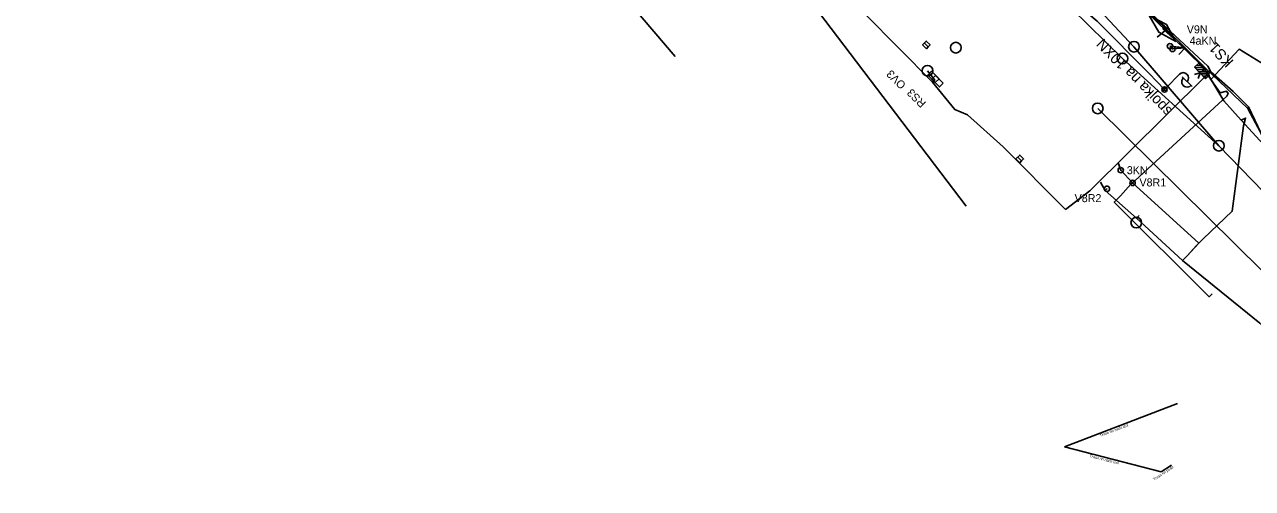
# Model space of a CAD drawing. Extents: x -748507 to -687366, y -1057342 to -1024924.
# Drawn here: x -745165 to -744934.9, y -1030359.4 to -1030272.6 of the extents above; entities that cross this region are included whole.
import ezdxf

# ---------------------------------------------------------------- set-up
doc = ezdxf.new("R2010")
doc.units = 0
for name, color, linetype in [('6kV - SŽDC', 7, 'Continuous'), ('DK + TKK - SŽDC', 7, 'Continuous'), ('DK - Pha Holešovice - Kralupy - ČD TELEMATIKA', 7, 'Continuous'), ('kanalizace ČD', 7, 'Continuous'), ('Sděl MK - SŽDC', 7, 'Continuous'), ('TK+DOK_Pha Holešovice - Kralupy', 7, 'Continuous'), ('Vedení NN - SŽDC', 7, 'Continuous'), ('ČEZ Distribuce - NN', 7, 'Continuous'), ('ČEZ Distribuce - VN', 7, 'Continuous')]:
    doc.layers.add(name, color=color, linetype=linetype)

msp = doc.modelspace()

# ---------------------------------------------------------------- linework, layer by layer
at = {"layer": '6kV - SŽDC'}
for points in [[(-744949.22, -1030275.73), (-744952.42, -1030273.99), (-744954.22, -1030270.83), (-744951.02, -1030272.57), (-744949.22, -1030275.73)], [(-744879.58, -1030350.79), (-744903.77, -1030325.05), (-744907.55, -1030322.07), (-744910.63, -1030318.43), (-744916.73, -1030311.64), (-744931.93, -1030295.39), (-744935.74, -1030288.25), (-744945.13, -1030279.35), (-744951.72, -1030273.28)]]:
    msp.add_lwpolyline(points, dxfattribs=at)
at = {"layer": 'DK + TKK - SŽDC'}
for p, q in [((-744950.39, -1030276.61), (-744950.29, -1030276.61)), ((-744949.91, -1030277.13), (-744949.81, -1030277.13)), ((-744944.22, -1030280.65), (-744945.63, -1030280.6)), ((-744944.58, -1030280.26), (-744945.43, -1030280.23)), ((-744944.94, -1030279.87), (-744945.04, -1030279.87)), ((-744943.85, -1030281.04), (-744945.27, -1030280.99)), ((-744943.49, -1030281.42), (-744944.91, -1030281.38)), ((-744943.13, -1030281.81), (-744944.54, -1030281.76)), ((-744943.12, -1030282.19), (-744944.18, -1030282.15)), ((-744943.51, -1030282.55), (-744943.82, -1030282.54)), ((-744959.61, -1030299.81), (-744959.51, -1030299.81)), ((-744962.19, -1030303.3), (-744962.09, -1030303.3)), ((-744957.38, -1030302.2), (-744957.28, -1030302.2))]:
    msp.add_line(p, q, dxfattribs=at)
for points in [[(-744950.99, -1030273.46), (-744961.24, -1030263.31), (-744962.68, -1030262.14), (-744962.78, -1030260.79), (-744961.45, -1030258.05), (-744958.78, -1030254.51)], [(-744950.99, -1030273.46), (-744952.76, -1030274.91)], [(-744947.52, -1030276.9), (-744950.34, -1030276.61)], [(-744947.52, -1030276.9), (-744949.86, -1030277.13)], [(-744947.52, -1030276.9), (-744948.67, -1030278.17)], [(-744943.67, -1030282.7), (-744945.72, -1030280.51), (-744944.99, -1030279.82), (-744942.94, -1030282.01), (-744943.67, -1030282.7)], [(-744945.08, -1030282.65), (-744944.7, -1030281.6), (-744945.77, -1030281.92)], [(-744910.5, -1030318.42), (-744932.1, -1030295.34), (-744935.6, -1030287.96), (-744938.52, -1030285.06), (-744942.69, -1030281.43), (-744944.43, -1030281.4)], [(-744943.82, -1030280.93), (-744944.33, -1030281.26)], [(-744936.98, -1030290.45), (-744936.16, -1030290.05), (-744936.59, -1030291.51), (-744938.68, -1030307.5), (-744944.14, -1030312.64), (-744944.9, -1030313.46), (-744945.42, -1030313.99), (-744947.14, -1030315.85), (-744948.01, -1030316.74)], [(-744944.9, -1030313.46), (-744957.33, -1030302.2), (-744959.56, -1030299.81), (-744960.04, -1030298.43)], [(-744948.01, -1030316.74), (-744956.64, -1030308.83), (-744962.49, -1030303.65), (-744963.37, -1030302.06)], [(-744962.49, -1030303.65), (-744962.14, -1030303.3)], [(-744956.64, -1030308.83), (-744956.08, -1030308.28)]]:
    msp.add_lwpolyline(points, dxfattribs=at)
msp.add_lwpolyline([(-744943.67, -1030282.7), (-744945.72, -1030280.51), (-744944.99, -1030279.82), (-744942.94, -1030282.01)], close=True, dxfattribs=at)
for centre in [(-744950.34, -1030276.61), (-744949.86, -1030277.13), (-744959.56, -1030299.81), (-744962.14, -1030303.3), (-744957.33, -1030302.2)]:
    msp.add_circle(centre, 0.5, dxfattribs=at)
at = {"layer": 'DK - Pha Holešovice - Kralupy - ČD TELEMATIKA'}
msp.add_lwpolyline([(-745043.07, -1030278.56), (-745100.09, -1030211.67), (-745164.97, -1030135.57)], dxfattribs=at)
at = {"layer": 'kanalizace ČD'}
for points in [[(-745024.73, -1030204.3), (-744990.5, -1030240.94), (-744957.08, -1030276.7), (-744941.18, -1030295.24)], [(-745019.83, -1030218.31), (-744984.72, -1030253.9), (-744959.23, -1030278.91), (-744941.18, -1030295.24), (-744920.38, -1030316.69)], [(-744995.64, -1030276.71), (-744995.99, -1030277.07), (-744996.71, -1030276.37), (-744996.01, -1030275.65), (-744995.29, -1030276.35), (-744995.64, -1030276.71), (-744996.36, -1030276.01)], [(-744927.88, -1030323.77), (-744963.88, -1030288.25)], [(-744978.13, -1030298.06), (-744978.48, -1030298.42), (-744979.2, -1030297.72), (-744978.5, -1030297), (-744977.78, -1030297.7), (-744978.13, -1030298.06), (-744978.85, -1030297.36)]]:
    msp.add_lwpolyline(points, dxfattribs=at)
for centre in [(-744990.47, -1030276.88), (-744957.08, -1030276.7), (-744959.23, -1030278.91), (-744963.88, -1030288.25), (-744941.18, -1030295.24), (-744956.65, -1030309.63)]:
    msp.add_circle(centre, 1, dxfattribs=at)
at = {"layer": 'Sděl MK - SŽDC'}
for points in [[(-744926.63, -1030301.78), (-744936.98, -1030290.45), (-744940.24, -1030286.84), (-744943.82, -1030280.93), (-744944.31, -1030280.12), (-744947.52, -1030276.9), (-744950.99, -1030273.46), (-744961.24, -1030263.31), (-744962.68, -1030262.14), (-744967.88, -1030268.59), (-744989.9, -1030244.56), (-744998.33, -1030235.25), (-745016.99, -1030215.52), (-745036.25, -1030195.28), (-745043.48, -1030188.11), (-745044.6, -1030189.16), (-745055.64, -1030177.25), (-745059.09, -1030172.81), (-745058.73, -1030172.54)], [(-744936.98, -1030290.45), (-744940.24, -1030286.84), (-744943.82, -1030280.93), (-744944.31, -1030280.12), (-744947.52, -1030276.9), (-744950.99, -1030273.46), (-744961.24, -1030263.31), (-744962.68, -1030262.14), (-744967.88, -1030268.59), (-744989.9, -1030244.56), (-744998.33, -1030235.25), (-744998.97, -1030236)], [(-744936.16, -1030290.05), (-744936.59, -1030291.51), (-744938.68, -1030307.5), (-744944.14, -1030312.64), (-744944.9, -1030313.46), (-744947.14, -1030315.85), (-744948.01, -1030316.74)], [(-744802.08, -1030437.28), (-744801.07, -1030436.31), (-744816.94, -1030419.31), (-744840.92, -1030394.05), (-744852.51, -1030381.42), (-744870.15, -1030362.35), (-744888.54, -1030342.9), (-744910.79, -1030318.89), (-744926.63, -1030301.78), (-744936.98, -1030290.45), (-744936.16, -1030290.05)], [(-744948.01, -1030316.74), (-744933.5, -1030328.45), (-744911.92, -1030348.93), (-744904.45, -1030356.11), (-744893.87, -1030366.46), (-744892.21, -1030367.96), (-744892.95, -1030369.25)]]:
    msp.add_lwpolyline(points, dxfattribs=at)
at = {"layer": 'TK+DOK_Pha Holešovice - Kralupy'}
for points in [[(-744818.78, -1030417.38), (-744840.92, -1030394.05), (-744852.51, -1030381.42), (-744870.15, -1030362.35), (-744888.54, -1030342.9), (-744910.79, -1030318.89), (-744926.63, -1030301.78), (-744936.98, -1030290.45), (-744940.24, -1030286.84), (-744944.31, -1030280.12), (-744947.52, -1030276.9), (-744950.99, -1030273.46), (-744961.24, -1030263.31), (-744962.68, -1030262.14), (-744967.88, -1030268.59)], [(-744753.74, -1030487.7), (-744773.86, -1030465.97), (-744790.82, -1030447.45), (-744803.68, -1030434.1), (-744818.78, -1030417.38), (-744840.92, -1030394.05), (-744852.51, -1030381.42), (-744870.15, -1030362.35), (-744888.54, -1030342.9), (-744910.79, -1030318.89), (-744926.63, -1030301.78), (-744936.98, -1030290.45), (-744940.24, -1030286.84), (-744944.31, -1030280.12), (-744947.52, -1030276.9), (-744950.99, -1030273.46), (-744962.68, -1030262.14)]]:
    msp.add_lwpolyline(points, dxfattribs=at)
at = {"layer": 'Vedení NN - SŽDC'}
for p, q in [((-744951.01, -1030284.36), (-744948.56, -1030281.86)), ((-744948.06, -1030282.35), (-744946.2, -1030284.17)), ((-744951.84, -1030284.86), (-744950.88, -1030284.85)), ((-744951.8, -1030284.49), (-744950.92, -1030284.48))]:
    msp.add_line(p, q, dxfattribs=at)
for points in [[(-744994.81, -1030283.36), (-745013.74, -1030264.21), (-745034.1, -1030242.59), (-745048.5, -1030227.4), (-745056.92, -1030218.3), (-745073.83, -1030200.47), (-745072.59, -1030200.31), (-745074.48, -1030198.37)], [(-744942.69, -1030281.43), (-744943.25, -1030280.33), (-744962.66, -1030262.24), (-744967.91, -1030268.6), (-744963.95, -1030271.94), (-744954.21, -1030281.71), (-744951.36, -1030284.72)], [(-744962.74, -1030262.23), (-744944.07, -1030280.6), (-744942.71, -1030282.86), (-744940.96, -1030285.32), (-744939.76, -1030285.01), (-744939.44, -1030285.45), (-744939.71, -1030285.96), (-744956.89, -1030301.75), (-744957.65, -1030302.44), (-744959.58, -1030304.63), (-744960.77, -1030305.79), (-744943.02, -1030323.5), (-744942.45, -1030322.96)], [(-744942.71, -1030282.86), (-744937.35, -1030277.17), (-744931.67, -1030280.67)], [(-744969.94, -1030307.16), (-744981.62, -1030295.46), (-744988.29, -1030289.47), (-744990.68, -1030288.45), (-744994.81, -1030283.36), (-744994.4, -1030282.97), (-744995.78, -1030281.19)], [(-744993.61, -1030282.7), (-744994.31, -1030283.42), (-744995.73, -1030282.02), (-744995.03, -1030281.3), (-744993.61, -1030282.7)], [(-744992.85, -1030283.5), (-744993.55, -1030284.22), (-744994.97, -1030282.82), (-744994.27, -1030282.1), (-744992.85, -1030283.5)], [(-744942.69, -1030281.43), (-744943.76, -1030282.27), (-744965.33, -1030303.66), (-744969.94, -1030307.16)]]:
    msp.add_lwpolyline(points, dxfattribs=at)
for centre, radius in [((-744995.78, -1030281.19), 1), ((-744951.36, -1030284.72), 0.5), ((-744951.36, -1030284.72), 0.5)]:
    msp.add_circle(centre, radius, dxfattribs=at)
for centre, start, end in [((-744947.85, -1030282.56), 315.5667, 135.5667), ((-744947.14, -1030283.27), 134.8642, 316.2693)]:
    msp.add_arc(centre, 1, start, end, dxfattribs=at)
at = {"layer": 'ČEZ Distribuce - NN'}
for points in [[(-744970.11, -1030351.64), (-744948.91, -1030343.51)], [(-744970.11, -1030351.64), (-744951.99, -1030356.32)], [(-744951.99, -1030356.32), (-744950.07, -1030355.04)]]:
    msp.add_lwpolyline(points, dxfattribs=at)
at = {"layer": 'ČEZ Distribuce - VN'}
msp.add_lwpolyline([(-744988.55, -1030306.53), (-745119.77, -1030133.93)], dxfattribs=at)

# ---------------------------------------------------------------- texts
at = {"layer": 'DK + TKK - SŽDC'}
for s, p in [('V9N', (-744947.19, -1030274.2)), ('4aKN', (-744946.66, -1030276.33)), ('3KN', (-744958.43, -1030300.57)), ('V8R1', (-744956.06, -1030302.86)), ('V8R2', (-744968.21, -1030305.8))]:
    msp.add_text(s, height=1.5, dxfattribs=at).set_placement(p)
msp.add_text('KS1', height=2, rotation=133.094, dxfattribs=at).set_placement((-744938.3, -1030279.42))
at = {"layer": 'TK+DOK_Pha Holešovice - Kralupy'}
msp.add_text('spojka na 10XN', height=2, rotation=133.7609, dxfattribs=at).set_placement((-744949.8, -1030288.63))
at = {"layer": 'Vedení NN - SŽDC'}
for s, rotation, p in [('OV3', 135.5225, (-744999.7, -1030283.74)), ('RS3', 135.5224, (-744995.94, -1030287.18))]:
    msp.add_text(s, height=1.5, rotation=rotation, dxfattribs=at).set_placement(p)
at = {"layer": 'ČEZ Distribuce - NN'}
for s, rotation, p in [('Trasa nn nadz izol', 20.9813, (-744963.38, -1030349.75)), ('Trasa nn nadz izol', 345.5176, (-744965.46, -1030353.51)), ('Trasa nn podz', 33.7038, (-744953.29, -1030357.96))]:
    msp.add_text(s, height=0.5, rotation=rotation, dxfattribs=at).set_placement(p)

doc.saveas('drawing.dxf')
